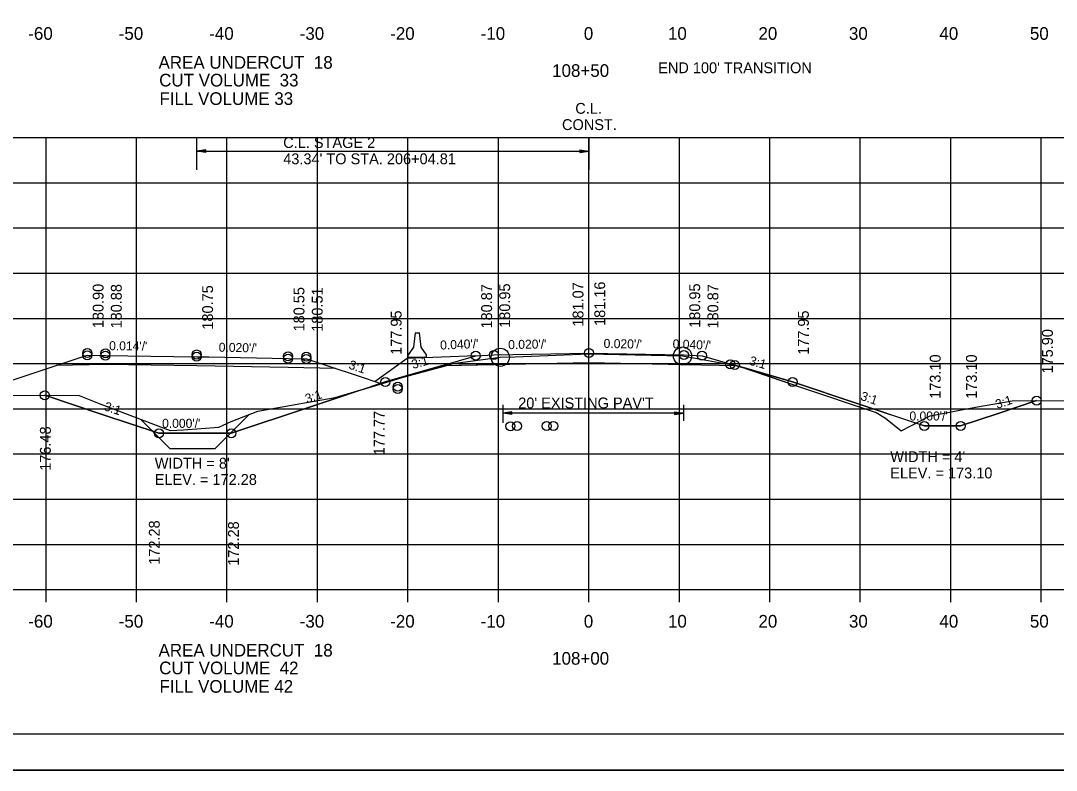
# Model space of a CAD drawing. Extents: x 1372132 to 1372465, y 380083 to 381790.
# Drawn here: x 1372239.2 to 1372353.7, y 381150.2 to 381233.1 of the extents above; entities that cross this region are included whole.
import ezdxf

# ---------------------------------------------------------------- set-up
doc = ezdxf.new("R2010")
doc.units = 0
for name, color, linetype in [('R_Alt Surface', 7, 'Continuous'), ('R_Axis', 7, 'Continuous'), ('R_Axis Annot', 7, 'Continuous'), ('R_Border', 7, 'Continuous'), ('R_Dimension', 7, 'Continuous'), ('R_Draft', 7, 'Continuous'), ('R_Erosion', 7, 'Continuous'), ('R_Exist Surface', 7, 'Continuous'), ('R_Fin Surface', 7, 'Continuous'), ('R_Grid', 7, 'Continuous'), ('R_No Plot', 7, 'Continuous'), ('R_Xsect Elev', 7, 'Continuous'), ('R_Xsect Slope', 7, 'Continuous')]:
    doc.layers.add(name, color=color, linetype=linetype)

msp = doc.modelspace()

# ---------------------------------------------------------------- linework, layer by layer
at = {"layer": 'R_Alt Surface'}
for points in [[(1372318.36, 381194.91), (1372312.51, 381195.03), (1372302.01, 381195.24), (1372291.51, 381195.03), (1372285.67, 381194.91)], [(1372274.01, 381194.61), (1372268.77, 381194.71), (1372258.67, 381194.91), (1372248.58, 381195.04), (1372243.13, 381194.94)]]:
    msp.add_lwpolyline(points, dxfattribs=at)
at = {"layer": 'R_Axis'}
for p, q in [((1372162.01, 381170.16), (1372442.01, 381170.16)), ((1372242.01, 381168.76), (1372242.01, 381170.16)), ((1372252.01, 381168.76), (1372252.01, 381170.16)), ((1372262.01, 381168.76), (1372262.01, 381170.16)), ((1372272.01, 381168.76), (1372272.01, 381170.16)), ((1372282.01, 381168.76), (1372282.01, 381170.16)), ((1372292.01, 381168.76), (1372292.01, 381170.16)), ((1372302.01, 381168.76), (1372302.01, 381170.16)), ((1372312.01, 381168.76), (1372312.01, 381170.16)), ((1372322.01, 381168.76), (1372322.01, 381170.16)), ((1372332.01, 381168.76), (1372332.01, 381170.16)), ((1372342.01, 381168.76), (1372342.01, 381170.16)), ((1372352.01, 381168.76), (1372352.01, 381170.16))]:
    msp.add_line(p, q, dxfattribs=at)
at = {"layer": 'R_Border'}
msp.add_line((1372460.19, 381154.16), (1372144.01, 381154.16), dxfattribs=at)
at = {"layer": 'R_Draft'}
for p, q in [((1372258.67, 381216.57), (1372258.67, 381220.16)), ((1372302.01, 381220.16), (1372302.01, 381216.57)), ((1372259.67, 381218.8), (1372258.67, 381218.65)), ((1372258.67, 381218.65), (1372302.01, 381218.65)), ((1372259.67, 381218.5), (1372258.67, 381218.65)), ((1372259.67, 381218.78), (1372258.84, 381218.65)), ((1372259.67, 381218.53), (1372258.84, 381218.65)), ((1372259.67, 381218.75), (1372259.01, 381218.65)), ((1372259.67, 381218.55), (1372259.01, 381218.65)), ((1372259.67, 381218.73), (1372259.18, 381218.65)), ((1372259.67, 381218.58), (1372259.18, 381218.65)), ((1372259.67, 381218.7), (1372259.35, 381218.65)), ((1372259.67, 381218.6), (1372259.35, 381218.65)), ((1372259.67, 381218.68), (1372259.51, 381218.65)), ((1372259.67, 381218.63), (1372259.51, 381218.65)), ((1372259.67, 381218.5), (1372259.67, 381218.8)), ((1372301.01, 381218.8), (1372302.01, 381218.65)), ((1372301.01, 381218.8), (1372301.01, 381218.5)), ((1372301.01, 381218.8), (1372302.01, 381218.65)), ((1372301.01, 381218.8), (1372301.01, 381218.5)), ((1372301.01, 381218.78), (1372301.85, 381218.65)), ((1372301.01, 381218.78), (1372301.85, 381218.65)), ((1372301.01, 381218.75), (1372301.68, 381218.65)), ((1372301.01, 381218.75), (1372301.68, 381218.65)), ((1372301.01, 381218.73), (1372301.51, 381218.65)), ((1372301.01, 381218.73), (1372301.51, 381218.65)), ((1372301.01, 381218.7), (1372301.34, 381218.65)), ((1372301.01, 381218.7), (1372301.34, 381218.65)), ((1372301.01, 381218.68), (1372301.17, 381218.65)), ((1372301.01, 381218.68), (1372301.17, 381218.65)), ((1372301.01, 381218.5), (1372302.01, 381218.65)), ((1372301.01, 381218.6), (1372301.34, 381218.65)), ((1372301.01, 381218.55), (1372301.68, 381218.65)), ((1372301.01, 381218.53), (1372301.85, 381218.65)), ((1372301.01, 381218.58), (1372301.51, 381218.65)), ((1372301.01, 381218.63), (1372301.17, 381218.65)), ((1372301.01, 381218.5), (1372302.01, 381218.65)), ((1372301.01, 381218.6), (1372301.34, 381218.65)), ((1372301.01, 381218.55), (1372301.68, 381218.65)), ((1372301.01, 381218.53), (1372301.85, 381218.65)), ((1372301.01, 381218.58), (1372301.51, 381218.65)), ((1372301.01, 381218.63), (1372301.17, 381218.65)), ((1372282.8, 381198.55), (1372282.62, 381196.96)), ((1372282.8, 381198.55), (1372283.3, 381198.55)), ((1372283.47, 381196.96), (1372283.3, 381198.55)), ((1372282.62, 381196.96), (1372282.05, 381196.13)), ((1372284.05, 381196.13), (1372283.47, 381196.96)), ((1372282.05, 381195.88), (1372282.05, 381196.13)), ((1372282.05, 381195.88), (1372284.05, 381195.88)), ((1372284.05, 381195.88), (1372284.05, 381196.13)), ((1372292.5, 381190.6), (1372292.5, 381188.59)), ((1372312.48, 381190.6), (1372312.48, 381188.82)), ((1372293.5, 381189.83), (1372292.5, 381189.68)), ((1372293.5, 381189.83), (1372292.5, 381189.68)), ((1372312.48, 381189.68), (1372292.5, 381189.68)), ((1372293.5, 381189.53), (1372292.5, 381189.68)), ((1372293.5, 381189.53), (1372292.5, 381189.68)), ((1372293.5, 381189.81), (1372292.67, 381189.68)), ((1372293.5, 381189.81), (1372292.67, 381189.68)), ((1372293.5, 381189.56), (1372292.67, 381189.68)), ((1372293.5, 381189.56), (1372292.67, 381189.68)), ((1372293.5, 381189.78), (1372292.84, 381189.68)), ((1372293.5, 381189.78), (1372292.84, 381189.68)), ((1372293.5, 381189.58), (1372292.84, 381189.68)), ((1372293.5, 381189.58), (1372292.84, 381189.68)), ((1372293.5, 381189.76), (1372293.01, 381189.68)), ((1372293.5, 381189.76), (1372293.01, 381189.68)), ((1372293.5, 381189.61), (1372293.01, 381189.68)), ((1372293.5, 381189.61), (1372293.01, 381189.68)), ((1372293.5, 381189.73), (1372293.17, 381189.68)), ((1372293.5, 381189.73), (1372293.17, 381189.68)), ((1372293.5, 381189.63), (1372293.17, 381189.68)), ((1372293.5, 381189.63), (1372293.17, 381189.68)), ((1372293.5, 381189.71), (1372293.34, 381189.68)), ((1372293.5, 381189.71), (1372293.34, 381189.68)), ((1372293.5, 381189.66), (1372293.34, 381189.68)), ((1372293.5, 381189.66), (1372293.34, 381189.68)), ((1372293.5, 381189.53), (1372293.5, 381189.83)), ((1372293.5, 381189.53), (1372293.5, 381189.83)), ((1372311.48, 381189.83), (1372312.48, 381189.68)), ((1372311.48, 381189.83), (1372311.48, 381189.53)), ((1372311.48, 381189.81), (1372312.31, 381189.68)), ((1372311.48, 381189.78), (1372312.14, 381189.68)), ((1372311.48, 381189.76), (1372311.97, 381189.68)), ((1372311.48, 381189.73), (1372311.81, 381189.68)), ((1372311.48, 381189.71), (1372311.64, 381189.68)), ((1372311.48, 381189.53), (1372312.48, 381189.68)), ((1372311.48, 381189.63), (1372311.81, 381189.68)), ((1372311.48, 381189.58), (1372312.14, 381189.68)), ((1372311.48, 381189.56), (1372312.31, 381189.68)), ((1372311.48, 381189.61), (1372311.97, 381189.68)), ((1372311.48, 381189.66), (1372311.64, 381189.68)), ((1372292.5, 381188.82), (1372292.5, 381188.82))]:
    msp.add_line(p, q, dxfattribs=at)
at = {"layer": 'R_Erosion'}
for p, q in [((1372281.92, 381195.73), (1372278.39, 381193.19)), ((1372289.51, 381196.03), (1372281.92, 381195.73)), ((1372260.71, 381185.76), (1372264.46, 381189.51)), ((1372255.71, 381185.76), (1372252.48, 381188.99)), ((1372255.71, 381185.76), (1372260.71, 381185.76))]:
    msp.add_line(p, q, dxfattribs=at)
at = {"layer": 'R_Exist Surface'}
msp.add_lwpolyline([(1372235.26, 381191.67), (1372245.67, 381191.63), (1372248.06, 381190.67), (1372255.72, 381187.76), (1372257.21, 381187.84), (1372261.11, 381188.12), (1372262.46, 381188.75), (1372265.43, 381189.88), (1372270.18, 381190.75), (1372273.98, 381191.39), (1372281.63, 381193.68), (1372286.98, 381195.15), (1372290.59, 381195.63), (1372292.22, 381195.85), (1372293.81, 381195.91), (1372302, 381196.24), (1372303.65, 381196.2), (1372312.36, 381196), (1372316.42, 381195.28), (1372318.36, 381194.95), (1372325.29, 381192.6), (1372333.77, 381189.75), (1372334.8, 381189.13), (1372336.53, 381187.73), (1372337.58, 381188.27), (1372339.72, 381189.37), (1372344.73, 381190.32), (1372348.79, 381191.05), (1372382, 381191.2)], dxfattribs=at)
at = {"layer": 'R_Fin Surface'}
for points in [[(1372241.88, 381191.65), (1372248.21, 381189.54), (1372254.49, 381187.45), (1372262.49, 381187.45), (1372271.03, 381190.29), (1372279.51, 381193.12), (1372285.67, 381194.91), (1372289.51, 381196.03), (1372291.51, 381196.11), (1372302.01, 381196.32), (1372312.51, 381196.11), (1372314.52, 381196.03), (1372318.36, 381194.91), (1372324.52, 381193.12), (1372331.76, 381190.71), (1372339.09, 381188.26), (1372343.09, 381188.26), (1372347.25, 381189.65), (1372351.49, 381191.06)], [(1372199.6, 381191.58), (1372205.21, 381188.81), (1372209.72, 381186.59), (1372212.24, 381186.6), (1372217.82, 381186.6), (1372219.13, 381187.03), (1372221.02, 381187.66), (1372231.75, 381191.19), (1372236.48, 381192.75), (1372241.71, 381194.47), (1372246.57, 381196.07), (1372247.93, 381196.05), (1372248.58, 381196.04), (1372251.05, 381196), (1372258.67, 381195.91), (1372258.96, 381195.91), (1372259.99, 381195.89), (1372268.77, 381195.71), (1372270.22, 381195.68), (1372270.79, 381195.67), (1372276.29, 381193.86), (1372279.11, 381192.93)]]:
    msp.add_lwpolyline(points, dxfattribs=at)
at = {"layer": 'R_Grid'}
for p, q in [((1372162.01, 381220.16), (1372442.01, 381220.16)), ((1372242.01, 381170.16), (1372242.01, 381220.16)), ((1372252.01, 381170.16), (1372252.01, 381220.16)), ((1372262.01, 381170.16), (1372262.01, 381220.16)), ((1372272.01, 381170.16), (1372272.01, 381220.16)), ((1372282.01, 381170.16), (1372282.01, 381220.16)), ((1372292.01, 381170.16), (1372292.01, 381220.16)), ((1372302.01, 381170.16), (1372302.01, 381220.16)), ((1372312.01, 381170.16), (1372312.01, 381220.16)), ((1372322.01, 381170.16), (1372322.01, 381220.16)), ((1372332.01, 381170.16), (1372332.01, 381220.16)), ((1372342.01, 381170.16), (1372342.01, 381220.16)), ((1372352.01, 381170.16), (1372352.01, 381220.16)), ((1372162.01, 381215.16), (1372442.01, 381215.16)), ((1372162.01, 381210.16), (1372442.01, 381210.16)), ((1372162.01, 381205.16), (1372442.01, 381205.16)), ((1372162.01, 381200.16), (1372442.01, 381200.16)), ((1372162.01, 381195.16), (1372442.01, 381195.16)), ((1372162.01, 381190.16), (1372442.01, 381190.16)), ((1372162.01, 381185.16), (1372442.01, 381185.16)), ((1372162.01, 381180.16), (1372442.01, 381180.16)), ((1372162.01, 381175.16), (1372442.01, 381175.16)), ((1372162.01, 381170.16), (1372442.01, 381170.16))]:
    msp.add_line(p, q, dxfattribs=at)
at = {"layer": 'R_No Plot'}
msp.add_line((1372131.61, 381150.18), (1372464.95, 381150.18), dxfattribs=at)
for points in [[(1372131.61, 381363.52), (1372464.95, 381363.52), (1372464.95, 381150.18), (1372131.61, 381150.18)], [(1372377.93, 381359.62), (1372377.93, 381349.74), (1372413.67, 381349.74), (1372413.67, 381346.82), (1372436.87, 381346.82), (1372436.87, 381322.49), (1372460.19, 381322.49), (1372460.19, 381154.16), (1372144.01, 381154.16), (1372144.01, 381359.62)], [(1372286.15, 381194.92), (1372286.98, 381195.15), (1372290.59, 381195.63), (1372292.22, 381195.85), (1372293.81, 381195.91), (1372302, 381196.24), (1372303.65, 381196.2), (1372312.36, 381196), (1372316.42, 381195.28), (1372318.36, 381194.95), (1372319.2, 381194.67), (1372318.36, 381194.91), (1372312.51, 381195.03), (1372302.01, 381195.24), (1372291.51, 381195.03)], [(1372277.35, 381192.4), (1372281.63, 381193.68), (1372286.15, 381194.92), (1372285.67, 381194.91), (1372279.51, 381193.12)], [(1372319.2, 381194.67), (1372325.29, 381192.6), (1372333.77, 381189.75), (1372334.8, 381189.13), (1372336.53, 381187.73), (1372337.58, 381188.27), (1372338.16, 381188.57), (1372331.76, 381190.71), (1372324.52, 381193.12)], [(1372241.88, 381191.65), (1372245.67, 381191.63), (1372248.06, 381190.67), (1372255.72, 381187.76), (1372257.21, 381187.84), (1372261.11, 381188.12), (1372262.46, 381188.75), (1372265.43, 381189.88), (1372270.18, 381190.75), (1372273.98, 381191.39), (1372277.35, 381192.4), (1372271.03, 381190.29), (1372262.49, 381187.45), (1372254.49, 381187.45), (1372248.21, 381189.54)], [(1372338.16, 381188.57), (1372339.72, 381189.37), (1372344.73, 381190.32), (1372348.79, 381191.05), (1372351.49, 381191.06), (1372347.25, 381189.65), (1372343.09, 381188.26), (1372339.09, 381188.26)]]:
    msp.add_lwpolyline(points, close=True, dxfattribs=at)
for centre, radius in [((1372246.57, 381196.32), 0.5), ((1372246.57, 381196.07), 0.5), ((1372248.58, 381196.29), 0.5), ((1372248.58, 381196.04), 0.5), ((1372258.67, 381196.16), 0.5), ((1372258.67, 381195.91), 0.5), ((1372268.77, 381195.96), 0.5), ((1372270.79, 381195.92), 0.5), ((1372289.51, 381196.03), 0.5), ((1372291.51, 381196.11), 0.5), ((1372292.22, 381195.85), 1), ((1372302.01, 381196.32), 0.5), ((1372312.36, 381196), 1), ((1372312.51, 381196.11), 0.5), ((1372314.52, 381196.03), 0.5), ((1372268.77, 381195.71), 0.5), ((1372270.79, 381195.67), 0.5), ((1372317.65, 381195.07), 0.5), ((1372318.14, 381194.99), 0.5), ((1372279.51, 381193.12), 0.5), ((1372280.89, 381192.59), 0.5), ((1372324.52, 381193.12), 0.5), ((1372241.88, 381191.65), 0.5), ((1372280.89, 381192.34), 0.5), ((1372351.49, 381191.06), 0.5), ((1372293.34, 381188.23), 0.5), ((1372294.08, 381188.24), 0.5), ((1372297.34, 381188.25), 0.5), ((1372298.09, 381188.25), 0.5), ((1372339.09, 381188.26), 0.5), ((1372343.09, 381188.26), 0.5), ((1372254.49, 381187.45), 0.5), ((1372262.49, 381187.45), 0.5)]:
    msp.add_circle(centre, radius, dxfattribs=at)
at = {"layer": 'R_Xsect Elev'}
msp.add_line((1372302.01, 381196.24), (1372302.01, 381206.24), dxfattribs=at)

# ---------------------------------------------------------------- texts
at = {"layer": 'R_Axis Annot'}
for s, p in [('-60', (1372240.05, 381230.96)), ('-50', (1372250.05, 381230.96)), ('-40', (1372260.05, 381230.96)), ('-30', (1372270.05, 381230.96)), ('-20', (1372280.05, 381230.96)), ('-10', (1372290.05, 381230.96)), ('0', (1372301.45, 381230.96)), ('10', (1372310.75, 381230.96)), ('20', (1372320.75, 381230.96)), ('30', (1372330.75, 381230.96)), ('40', (1372340.75, 381230.96)), ('50', (1372350.75, 381230.96)), ('AREA UNDERCUT  18', (1372254.45, 381227.76)), ('CUT VOLUME  33', (1372254.52, 381225.8)), ('108+50', (1372297.95, 381226.86)), ('FILL VOLUME 33', (1372254.55, 381223.76)), ('-60', (1372240.05, 381165.96)), ('-50', (1372250.05, 381165.96)), ('-40', (1372260.05, 381165.96)), ('-30', (1372270.05, 381165.96)), ('-20', (1372280.05, 381165.96)), ('-10', (1372290.05, 381165.96)), ('0', (1372301.45, 381165.96)), ('10', (1372310.75, 381165.96)), ('20', (1372320.75, 381165.96)), ('30', (1372330.75, 381165.96)), ('40', (1372340.75, 381165.96)), ('50', (1372350.75, 381165.96)), ('AREA UNDERCUT  18', (1372254.45, 381162.76)), ('108+00', (1372297.95, 381161.86)), ('CUT VOLUME  42', (1372254.52, 381160.8)), ('FILL VOLUME 42', (1372254.55, 381158.76))]:
    msp.add_text(s, height=1.4, dxfattribs=at).set_placement(p)
at = {"layer": 'R_Dimension'}
for s, p in [("WIDTH = 4'", (1372335.32, 381184.26)), ("WIDTH = 8'", (1372254.03, 381183.54)), ('ELEV. = 172.28', (1372254.03, 381181.74)), ('ELEV. = 173.10', (1372335.32, 381182.46))]:
    msp.add_text(s, height=1.2, dxfattribs=at).set_placement(p)
at = {"layer": 'R_Draft'}
for s, p in [("END 100' TRANSITION", (1372309.67, 381227.27)), ('C.L. ', (1372300.51, 381222.78)), ('CONST. ', (1372299.04, 381220.98)), ('C.L. STAGE 2', (1372268.23, 381219)), ("43.34' TO STA. 206+04.81", (1372268.23, 381217.2)), ("20' EXISTING PAV'T", (1372294.2, 381190.2))]:
    msp.add_text(s, height=1.2, rotation=360, dxfattribs=at).set_placement(p)
at = {"layer": 'R_Xsect Elev'}
for s, p in [('180.90', (1372248.37, 381199.07)), ('180.88', (1372250.38, 381199.04)), ('180.75', (1372260.47, 381198.91)), ('180.55', (1372270.57, 381198.71)), ('180.51', (1372272.59, 381198.67)), ('180.87', (1372291.31, 381199.03)), ('180.95', (1372293.31, 381199.11)), ('181.07', (1372301.41, 381199.24)), ('181.16', (1372303.81, 381199.32)), ('180.95', (1372314.31, 381199.11)), ('180.87', (1372316.32, 381199.03)), ('177.95', (1372281.31, 381196.12)), ('177.95', (1372326.32, 381196.12)), ('175.90', (1372353.29, 381194.06)), ('173.10', (1372340.89, 381191.26)), ('173.10', (1372344.89, 381191.26)), ('177.77', (1372279.43, 381185.02)), ('176.48', (1372242.54, 381183.3)), ('172.28', (1372254.58, 381172.91)), ('172.28', (1372263.33, 381172.8))]:
    msp.add_text(s, height=1.2, rotation=90, dxfattribs=at).set_placement(p)
at = {"layer": 'R_Xsect Slope'}
for s, rotation, p in [("0.014'/'", 359.2654, (1372248.98, 381196.64)), ("0.020'/'", 358.8694, (1372261.09, 381196.47)), ("0.040'/'", 2.2906, (1372285.59, 381196.7)), ("0.020'/'", 1.1458, (1372293.1, 381196.75)), ("0.020'/'", 358.8542, (1372303.63, 381196.89)), ("0.040'/'", 357.7094, (1372311.25, 381196.85)), ('3:1', 341.7414, (1372275.39, 381194.62)), ('3:1', 16.2602, (1372282.58, 381194.55)), ('3:1', 343.7398, (1372319.66, 381195.06)), ('3:1', 18.4332, (1372270.84, 381190.76)), ('3:1', 341.5668, (1372331.96, 381191.16)), ('3:1', 341.5651, (1372248.35, 381190.02)), ('3:1', 18.4349, (1372347.13, 381190.14)), ("0.000'/'", 360, (1372337.44, 381188.86)), ("0.000'/'", 360, (1372254.84, 381188.05))]:
    msp.add_text(s, height=1, rotation=rotation, dxfattribs=at).set_placement(p)

doc.saveas('drawing.dxf')
